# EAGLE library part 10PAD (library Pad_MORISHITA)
for flat cable
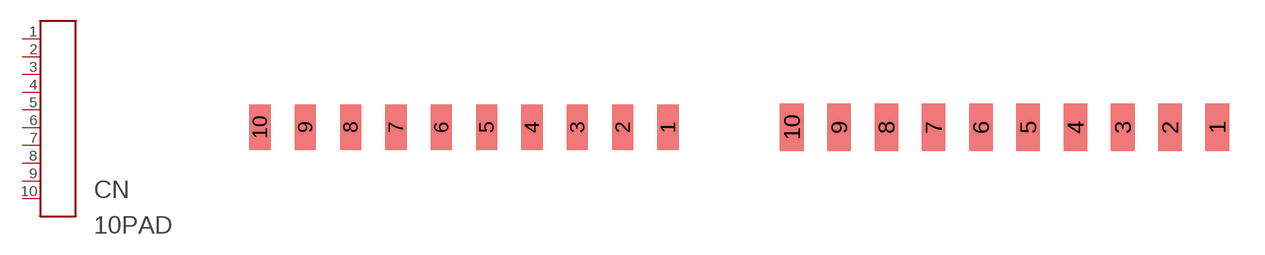
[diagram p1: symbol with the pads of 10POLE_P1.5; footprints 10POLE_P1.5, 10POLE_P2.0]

Designator prefix CN

## 10PAD-1.5  [10POLE_P1.5]
1  P$1
2  P$2
3  P$3
4  P$4
5  P$5
6  P$6
7  P$7
8  P$8
9  P$9
10  P$10

## 10PAD-2.0  [10POLE_P2.0]
Pads as for 10POLE_P1.5

## 10PAD-2.54BS  [10POLE_P2.54_BOTH_SIDE]
Pads as for 10POLE_P1.5

## Footprint 10POLE_P1.5 (pad centres in mm)
1.5mm pitch
smd 0.7 x 1.5: 1 6.75,0; 2 5.25,0; 3 3.75,0; 4 2.25,0; 5 0.75,0; 6 -0.75,0; 7 -2.25,0; 8 -3.75,0; 9 -5.25,0; 10 -6.75,0

## Footprint 10POLE_P2.0 (pad centres in mm)
smd 1 x 2: 1 9,0; 2 7,0; 3 5,0; 4 3,0; 5 1,0; 6 -1,0; 7 -3,0; 8 -5,0; 9 -7,0; 10 -9,0

## Footprint 10POLE_P2.54_BOTH_SIDE (pad centres in mm)
smd 1.5 x 3: 1 5.08,0; 3 2.54,0; 5 0,0; 7 -2.54,0; 9 -5.08,0
smd 1.5 x 3 bottom: 2 5.08,0; 4 2.54,0; 6 0,0; 8 -2.54,0; 10 -5.08,0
